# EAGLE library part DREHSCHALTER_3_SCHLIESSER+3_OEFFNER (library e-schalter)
3 Ein-, 3 Aus-Schalter, Betätigung durch Drehen
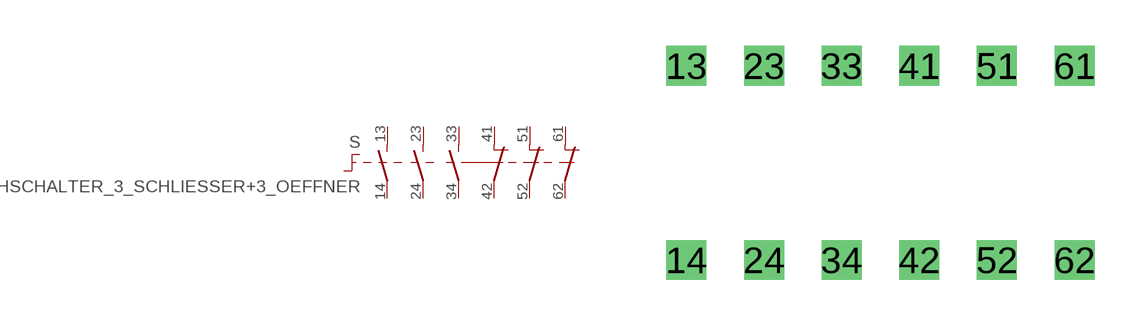
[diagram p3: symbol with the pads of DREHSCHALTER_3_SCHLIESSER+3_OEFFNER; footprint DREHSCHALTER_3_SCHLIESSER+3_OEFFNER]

Designator prefix S

## DREHSCHALTER_3_SCHLIESSER+3_OEFFNER  [DREHSCHALTER_3_SCHLIESSER+3_OEFFNER]
13  13  pas
14  14  pas
23  23  pas
24  24  pas
33  33  pas
34  34  pas
41  41  pas
42  42  pas
51  51  pas
52  52  pas
61  61  pas
62  62  pas

## Footprint DREHSCHALTER_3_SCHLIESSER+3_OEFFNER (pad centres in mm)
Dummy
drill 0.8 square: 13 -6.35,3.175; 14 -6.35,-3.175; 23 -3.81,3.175; 24 -3.81,-3.175; 33 -1.27,3.175; 34 -1.27,-3.175; 41 1.27,3.175; 42 1.27,-3.175; 51 3.81,3.175; 52 3.81,-3.175; 61 6.35,3.175; 62 6.35,-3.175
